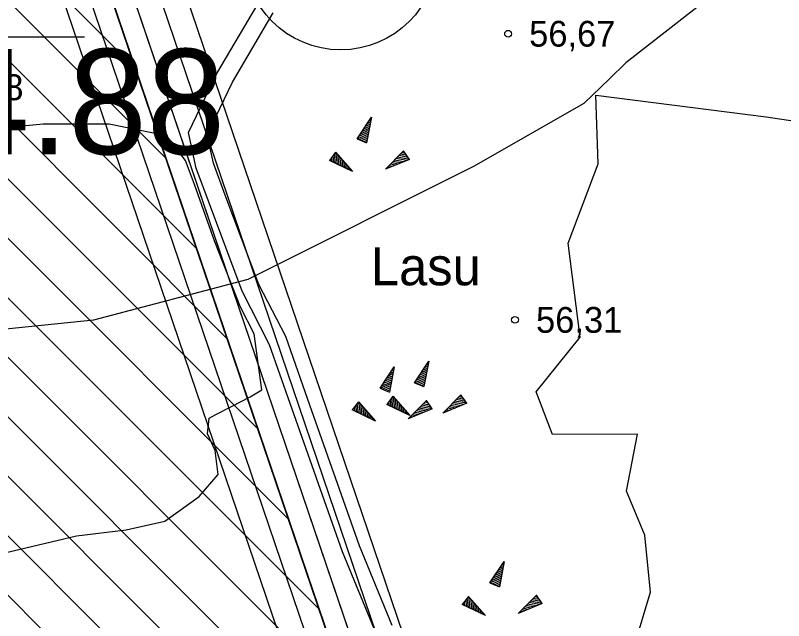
# Model space of a CAD drawing. Extents: x 532503 to 539665, y 6557663 to 6561526.
# Drawn here: x 534874.3 to 534947.4, y 6559690.1 to 6559747.6 of the extents above; entities that cross this region are included whole.
import ezdxf

# ---------------------------------------------------------------- set-up
doc = ezdxf.new("R2010")
doc.units = 0
for name, color, linetype in [('Default', 7, 'Continuous'), ('HALJASTUS', 7, 'Continuous'), ('illumineerimisjooned', 7, 'Continuous'), ('jääkpaksus', 7, 'Continuous'), ('Kaevandatud ala', 7, 'Continuous'), ('kataster', 7, 'Continuous'), ('KORGUS-EH2000', 7, 'Continuous'), ('Lamami horisontaal_EH2000', 7, 'Continuous'), ('ME_aktiivne', 7, 'Continuous'), ('MOOTKORG', 7, 'Continuous'), ('PIIR', 7, 'Continuous'), ('PIIR_me', 7, 'Continuous'), ('Plokid', 7, 'Continuous'), ('RELJEEF', 7, 'Continuous'), ('TM_aktiivne', 7, 'Continuous')]:
    doc.layers.add(name, color=color, linetype=linetype)

# ---------------------------------------------------------------- blocks, each defined once
blk = doc.blocks.new('POINT_DISPLAY')
at = {"layer": 'Default'}
blk.add_line((0, 0), (0, 0), dxfattribs=at)

msp = doc.modelspace()

# ---------------------------------------------------------------- linework, layer by layer
at = {"layer": 'illumineerimisjooned'}
for points in [[(534195.15, 6559981.187), (534198.982, 6559981.551), (535160.123, 6560071.768), (535418.528, 6559993.818), (535458.873, 6559929.252), (535494.628, 6559867.696), (535482.599, 6559826.001), (535251.738, 6559649.676), (535250.358, 6559648.526), (535180.445, 6559687.333), (534941.147, 6559814.594), (534876.935, 6559774.719), (534959.617, 6559531.323), (534733.77, 6559483.152), (534375.905, 6559461.866), (534195.514, 6559444.474)], [(535103.273, 6559501.74), (534971.344, 6559496.804), (534876.945, 6559774.719), (534941.147, 6559814.604), (535178.869, 6559688.171)], [(534960.711, 6559535.564), (534879.83, 6559773.686), (534941.24, 6559811.836), (535177.962, 6559685.935)]]:
    msp.add_lwpolyline(points, dxfattribs=at)
msp.add_lwpolyline([(534967.673, 6560049.69), (534974.155, 6559828.082), (535058.693, 6559883.051), (535223.499, 6560002.448), (535218.56, 6560049.918), (535415.933, 6559990.422), (535455.447, 6559927.188), (535490.312, 6559867.164), (535479.121, 6559828.379), (535249.574, 6559653.049), (535182.36, 6559690.845), (534940.993, 6559819.216), (534872.135, 6559776.441), (534954.369, 6559534.338), (534950.911, 6559533.67), (534733.22, 6559487.117), (534375.585, 6559465.864), (534199.951, 6559448.922), (533951.788, 6559660.129), (534200.214, 6559977.649), (534931.627, 6560046.309)], close=True, dxfattribs=at)
at = {"layer": 'jääkpaksus'}
msp.add_lwpolyline([(534864.921, 6559740.761), (534864.921, 6559745.561), (534880.921, 6559745.561)], dxfattribs=at)
at = {"layer": 'Kaevandatud ala'}
for p, q in [((534849.041, 6559779.274), (534885.756, 6559742.56)), ((534844.74, 6559777.919), (534888.666, 6559733.993)), ((534948.504, 6559557.824), (534874.54, 6559775.58)), ((534851.209, 6559765.793), (534891.575, 6559725.426)), ((534846.438, 6559764.906), (534894.485, 6559716.86)), ((534841.418, 6559764.27), (534897.395, 6559708.293)), ((534846.197, 6559748.178), (534903.214, 6559691.16)), ((534841.524, 6559747.193), (534906.124, 6559682.593)), ((534852.844, 6559747.187), (534900.305, 6559699.727)), ((534837.222, 6559745.838), (534909.034, 6559674.027)), ((534832.452, 6559744.952), (534911.944, 6559665.46)), ((534821.764, 6559744.326), (534917.763, 6559648.327)), ((534827.089, 6559744.658), (534914.853, 6559656.894))]:
    msp.add_line(p, q, dxfattribs=at)
at = {"layer": 'kataster'}
for points in [[(533947.7, 6559658.95), (533949.2, 6559955.8), (534198.28, 6559979.48), (535159.89, 6560069.73), (535417.31, 6559992.13), (535457.22, 6559928.24), (535504.86, 6559846.09), (535250.3, 6559650.84), (535181.52, 6559689.04), (534941.15, 6559817.08), (534874.65, 6559775.26), (534957.01, 6559532.73), (534735.22, 6559485.45), (534375.71, 6559463.85), (534199.28, 6559446.9), (534122.84, 6559439.44), (534110.45, 6559447.36), (534092.53, 6559453.94), (534085.13, 6559454.75)], [(534957.01, 6559532.73), (534874.65, 6559775.26), (534941.15, 6559817.08), (535181.52, 6559689.04), (535104.64, 6559499.79), (534969.93, 6559494.75)]]:
    msp.add_lwpolyline(points, close=True, dxfattribs=at)
at = {"layer": 'KORGUS-EH2000'}
for centre in [(534921.171, 6559745.851), (534921.824, 6559718.655)]:
    msp.add_circle(centre, 0.32, dxfattribs=at)
at = {"layer": 'Lamami horisontaal_EH2000'}
msp.add_lwpolyline([(534948.61, 6559756.736), (534944.621, 6559753.17), (534942.275, 6559750.842), (534932.369, 6559743.101), (534930.796, 6559741.554), (534928.37, 6559739.225), (534917.897, 6559733.223), (534896.45, 6559722.499), (534881.767, 6559718.623), (534861.677, 6559716.58), (534841.918, 6559714.402), (534826.048, 6559713.586), (534808.234, 6559712.485), (534790.42, 6559711.19), (534772.606, 6559709.668)], dxfattribs=at)
at = {"layer": 'ME_aktiivne'}
msp.add_lwpolyline([(534874.54, 6559775.58), (534941.07, 6559816.91), (535181.4, 6559689.09), (535131.71, 6559566.56), (534957, 6559532.81)], close=True, dxfattribs=at)
at = {"layer": 'PIIR'}
msp.add_circle((534905.265, 6559753.513), 9.2, dxfattribs=at)
at = {"layer": 'PIIR_me'}
msp.add_lwpolyline([(534441.63, 6560002.32), (534688.17, 6560025.46), (534931.44, 6560048.3), (534969.61, 6560051.877), (534976.05, 6559831.7), (535057.56, 6559884.7), (535221.39, 6560003.39), (535216.26, 6560052.7), (535417.23, 6559992.12), (535457.16, 6559928.22), (535492.47, 6559867.43), (535480.86, 6559827.19), (535250.12, 6559650.95), (535250.12, 6559650.95), (535181.4, 6559689.09), (534941.07, 6559816.91), (534874.54, 6559775.58), (534957, 6559532.81), (534951.31, 6559531.71), (534733.49, 6559485.13), (534485.11, 6559470.37)], dxfattribs=at)
at = {"layer": 'Plokid'}
for points in [[(535473.831, 6559827.358), (535249.729, 6559656.195), (535183.501, 6559692.956), (534940.9, 6559821.974), (534869.24, 6559777.474), (534950.465, 6559538.369)], [(534961.532, 6559540.611), (534882.716, 6559772.654), (534941.333, 6559809.068), (535174.925, 6559684.832)]]:
    msp.add_lwpolyline(points, dxfattribs=at)
at = {"layer": 'RELJEEF'}
for p, q in [((534906.833, 6559735.866), (534908.177, 6559737.914)), ((534908.177, 6559737.914), (534907.729, 6559735.498)), ((534907.777, 6559737.306), (534908.097, 6559737.434)), ((534907.937, 6559737.546), (534908.129, 6559737.626)), ((534908.097, 6559737.786), (534908.161, 6559737.818)), ((534907.153, 6559736.346), (534907.953, 6559736.682)), ((534907.313, 6559736.586), (534907.713, 6559736.762)), ((534907.473, 6559736.826), (534908.017, 6559737.066)), ((534907.633, 6559737.066), (534908.049, 6559737.258)), ((534907.713, 6559736.762), (534907.985, 6559736.874)), ((534906.833, 6559735.866), (534907.873, 6559736.314)), ((534906.993, 6559736.106), (534907.905, 6559736.49)), ((534907.041, 6559735.786), (534907.841, 6559736.122)), ((534906.833, 6559735.866), (534907.729, 6559735.498)), ((534907.249, 6559735.69), (534907.809, 6559735.93)), ((534907.473, 6559735.61), (534907.777, 6559735.738)), ((534907.681, 6559735.53), (534907.729, 6559735.546)), ((534904.781, 6559734.584), (534904.189, 6559733.816)), ((534904.781, 6559734.584), (534906.397, 6559732.76)), ((534904.781, 6559734.584), (534904.925, 6559733.464)), ((534909.515, 6559732.968), (534911.243, 6559734.712)), ((534911.403, 6559734.472), (534911.083, 6559734.536)), ((534911.275, 6559734.664), (534911.211, 6559734.664)), ((534911.787, 6559733.912), (534911.243, 6559734.712)), ((534906.397, 6559732.76), (534904.189, 6559733.816)), ((534904.221, 6559733.864), (534904.237, 6559733.8)), ((534904.365, 6559734.04), (534904.413, 6559733.72)), ((534904.509, 6559734.232), (534904.589, 6559733.64)), ((534904.637, 6559734.408), (534904.749, 6559733.544)), ((534904.973, 6559734.376), (534905.101, 6559733.384)), ((534905.165, 6559734.152), (534905.277, 6559733.304)), ((534905.357, 6559733.944), (534905.405, 6559733.496)), ((534911.787, 6559733.912), (534909.515, 6559732.968)), ((534911.243, 6559733.688), (534910.395, 6559733.848)), ((534911.515, 6559733.8), (534910.539, 6559733.992)), ((534911.787, 6559733.912), (534910.667, 6559734.12)), ((534911.659, 6559734.088), (534910.811, 6559734.264)), ((534911.531, 6559734.28), (534910.939, 6559734.392)), ((534905.405, 6559733.496), (534905.453, 6559733.208)), ((534905.533, 6559733.72), (534905.629, 6559733.128)), ((534905.725, 6559733.512), (534905.789, 6559733.048)), ((534905.917, 6559733.288), (534905.965, 6559732.968)), ((534906.109, 6559733.08), (534906.141, 6559732.872)), ((534909.643, 6559733.016), (534909.595, 6559733.032)), ((534909.915, 6559733.128), (534909.723, 6559733.176)), ((534910.187, 6559733.24), (534909.851, 6559733.304)), ((534910.443, 6559733.352), (534909.995, 6559733.448)), ((534910.715, 6559733.464), (534910.123, 6559733.576)), ((534910.555, 6559733.656), (534910.267, 6559733.72)), ((534910.987, 6559733.576), (534910.555, 6559733.656)), ((534906.301, 6559732.856), (534906.317, 6559732.792)), ((534909.008, 6559712.152), (534910.352, 6559714.2)), ((534910.352, 6559714.2), (534909.904, 6559711.784)), ((534910.272, 6559714.072), (534910.336, 6559714.104)), ((534912.281, 6559712.68), (534913.625, 6559714.728)), ((534913.081, 6559713.88), (534913.497, 6559714.072)), ((534913.625, 6559714.728), (534913.177, 6559712.312)), ((534913.225, 6559714.12), (534913.545, 6559714.248)), ((534913.385, 6559714.36), (534913.577, 6559714.44)), ((534913.545, 6559714.6), (534913.609, 6559714.632)), ((534909.648, 6559713.112), (534910.192, 6559713.352)), ((534909.808, 6559713.352), (534910.224, 6559713.544)), ((534909.952, 6559713.592), (534910.272, 6559713.72)), ((534910.112, 6559713.832), (534910.304, 6559713.912)), ((534912.601, 6559713.16), (534913.401, 6559713.496)), ((534912.761, 6559713.4), (534913.161, 6559713.576)), ((534912.921, 6559713.64), (534913.465, 6559713.88)), ((534913.161, 6559713.576), (534913.433, 6559713.688)), ((534909.008, 6559712.152), (534910.048, 6559712.6)), ((534909.168, 6559712.392), (534910.08, 6559712.776)), ((534909.328, 6559712.632), (534910.128, 6559712.968)), ((534909.488, 6559712.872), (534909.888, 6559713.048)), ((534909.888, 6559713.048), (534910.16, 6559713.16)), ((534912.281, 6559712.68), (534913.321, 6559713.128)), ((534912.281, 6559712.68), (534913.177, 6559712.312)), ((534912.441, 6559712.92), (534913.353, 6559713.304)), ((534912.489, 6559712.6), (534913.289, 6559712.936)), ((534912.697, 6559712.504), (534913.257, 6559712.744)), ((534909.008, 6559712.152), (534909.904, 6559711.784)), ((534909.216, 6559712.072), (534910.016, 6559712.408)), ((534909.424, 6559711.976), (534909.984, 6559712.216)), ((534909.648, 6559711.896), (534909.952, 6559712.024)), ((534912.921, 6559712.424), (534913.225, 6559712.552)), ((534913.129, 6559712.344), (534913.177, 6559712.36)), ((534910.229, 6559711.397), (534909.637, 6559710.629)), ((534909.856, 6559711.816), (534909.904, 6559711.832)), ((534910.085, 6559711.221), (534910.197, 6559710.357)), ((534910.229, 6559711.397), (534911.845, 6559709.573)), ((534910.229, 6559711.397), (534910.373, 6559710.277)), ((534910.421, 6559711.189), (534910.549, 6559710.197)), ((534914.963, 6559709.781), (534916.691, 6559711.525)), ((534916.979, 6559711.093), (534916.387, 6559711.205)), ((534916.851, 6559711.285), (534916.531, 6559711.349)), ((534916.723, 6559711.477), (534916.659, 6559711.477)), ((534917.235, 6559710.725), (534916.691, 6559711.525)), ((534906.956, 6559710.869), (534906.364, 6559710.101)), ((534906.684, 6559710.517), (534906.764, 6559709.925)), ((534906.812, 6559710.693), (534906.924, 6559709.829)), ((534906.956, 6559710.869), (534908.572, 6559709.045)), ((534906.956, 6559710.869), (534907.1, 6559709.749)), ((534907.148, 6559710.661), (534907.276, 6559709.669)), ((534907.34, 6559710.437), (534907.452, 6559709.589)), ((534911.845, 6559709.573), (534909.637, 6559710.629)), ((534909.669, 6559710.677), (534909.685, 6559710.613)), ((534909.813, 6559710.853), (534909.861, 6559710.533)), ((534909.957, 6559711.045), (534910.037, 6559710.453)), ((534910.613, 6559710.965), (534910.725, 6559710.117)), ((534910.805, 6559710.757), (534910.853, 6559710.309)), ((534910.981, 6559710.533), (534911.077, 6559709.941)), ((534911.689, 6559709.253), (534913.417, 6559710.997)), ((534913.961, 6559710.197), (534912.841, 6559710.405)), ((534913.833, 6559710.373), (534912.985, 6559710.549)), ((534913.705, 6559710.565), (534913.113, 6559710.677)), ((534913.577, 6559710.757), (534913.257, 6559710.821)), ((534913.449, 6559710.949), (534913.385, 6559710.949)), ((534913.961, 6559710.197), (534913.417, 6559710.997)), ((534917.235, 6559710.725), (534914.963, 6559709.781)), ((534916.003, 6559710.469), (534915.715, 6559710.533)), ((534916.691, 6559710.501), (534915.843, 6559710.661)), ((534916.963, 6559710.613), (534915.987, 6559710.805)), ((534916.435, 6559710.389), (534916.003, 6559710.469)), ((534917.235, 6559710.725), (534916.115, 6559710.933)), ((534917.107, 6559710.901), (534916.259, 6559711.077)), ((534908.572, 6559709.045), (534906.364, 6559710.101)), ((534906.396, 6559710.149), (534906.412, 6559710.085)), ((534906.54, 6559710.325), (534906.588, 6559710.005)), ((534907.532, 6559710.229), (534907.58, 6559709.781)), ((534907.58, 6559709.781), (534907.628, 6559709.493)), ((534907.708, 6559710.005), (534907.804, 6559709.413)), ((534907.9, 6559709.797), (534907.964, 6559709.333)), ((534910.853, 6559710.309), (534910.901, 6559710.021)), ((534911.173, 6559710.325), (534911.237, 6559709.861)), ((534911.365, 6559710.101), (534911.413, 6559709.781)), ((534911.557, 6559709.893), (534911.589, 6559709.685)), ((534913.961, 6559710.197), (534911.689, 6559709.253)), ((534911.749, 6559709.669), (534911.765, 6559709.605)), ((534912.617, 6559709.637), (534912.169, 6559709.733)), ((534912.889, 6559709.749), (534912.297, 6559709.861)), ((534912.729, 6559709.941), (534912.441, 6559710.005)), ((534913.417, 6559709.973), (534912.569, 6559710.133)), ((534913.689, 6559710.085), (534912.713, 6559710.277)), ((534913.161, 6559709.861), (534912.729, 6559709.941)), ((534915.091, 6559709.829), (534915.043, 6559709.845)), ((534915.363, 6559709.941), (534915.171, 6559709.989)), ((534915.635, 6559710.053), (534915.299, 6559710.117)), ((534915.891, 6559710.165), (534915.443, 6559710.261)), ((534916.163, 6559710.277), (534915.571, 6559710.389)), ((534908.092, 6559709.573), (534908.14, 6559709.253)), ((534908.284, 6559709.365), (534908.316, 6559709.157)), ((534908.476, 6559709.141), (534908.492, 6559709.077)), ((534911.817, 6559709.301), (534911.769, 6559709.317)), ((534912.089, 6559709.413), (534911.897, 6559709.461)), ((534912.361, 6559709.525), (534912.025, 6559709.589)), ((534919.447, 6559693.659), (534920.791, 6559695.707)), ((534920.791, 6559695.707), (534920.343, 6559693.291)), ((534920.391, 6559695.099), (534920.711, 6559695.227)), ((534920.551, 6559695.339), (534920.743, 6559695.419)), ((534920.711, 6559695.579), (534920.775, 6559695.611)), ((534919.767, 6559694.139), (534920.567, 6559694.475)), ((534919.927, 6559694.379), (534920.327, 6559694.555)), ((534920.087, 6559694.619), (534920.631, 6559694.859)), ((534920.247, 6559694.859), (534920.663, 6559695.051)), ((534920.327, 6559694.555), (534920.599, 6559694.667)), ((534919.447, 6559693.659), (534920.487, 6559694.107)), ((534919.447, 6559693.659), (534920.343, 6559693.291)), ((534919.607, 6559693.899), (534920.519, 6559694.283)), ((534919.655, 6559693.579), (534920.455, 6559693.915)), ((534919.863, 6559693.483), (534920.423, 6559693.723)), ((534920.087, 6559693.403), (534920.391, 6559693.531)), ((534920.295, 6559693.323), (534920.343, 6559693.339)), ((534917.395, 6559692.377), (534916.803, 6559691.609)), ((534917.251, 6559692.201), (534917.363, 6559691.337)), ((534917.395, 6559692.377), (534919.011, 6559690.553)), ((534917.395, 6559692.377), (534917.539, 6559691.257)), ((534917.587, 6559692.169), (534917.715, 6559691.177)), ((534922.129, 6559690.761), (534923.857, 6559692.505)), ((534924.145, 6559692.073), (534923.553, 6559692.185)), ((534924.017, 6559692.265), (534923.697, 6559692.329)), ((534923.889, 6559692.457), (534923.825, 6559692.457)), ((534924.401, 6559691.705), (534923.857, 6559692.505)), ((534919.011, 6559690.553), (534916.803, 6559691.609)), ((534916.835, 6559691.657), (534916.851, 6559691.593)), ((534916.979, 6559691.833), (534917.027, 6559691.513)), ((534917.123, 6559692.025), (534917.203, 6559691.433)), ((534917.779, 6559691.945), (534917.891, 6559691.097)), ((534917.971, 6559691.737), (534918.019, 6559691.289)), ((534918.147, 6559691.513), (534918.243, 6559690.921)), ((534924.401, 6559691.705), (534922.129, 6559690.761)), ((534923.169, 6559691.449), (534922.881, 6559691.513)), ((534923.857, 6559691.481), (534923.009, 6559691.641)), ((534924.129, 6559691.593), (534923.153, 6559691.785)), ((534923.601, 6559691.369), (534923.169, 6559691.449)), ((534924.401, 6559691.705), (534923.281, 6559691.913)), ((534924.273, 6559691.881), (534923.425, 6559692.057)), ((534918.019, 6559691.289), (534918.067, 6559691.001)), ((534918.339, 6559691.305), (534918.403, 6559690.841)), ((534918.531, 6559691.081), (534918.579, 6559690.761)), ((534918.723, 6559690.873), (534918.755, 6559690.665)), ((534922.257, 6559690.809), (534922.209, 6559690.825)), ((534922.529, 6559690.921), (534922.337, 6559690.969)), ((534922.801, 6559691.033), (534922.465, 6559691.097)), ((534923.057, 6559691.145), (534922.609, 6559691.241)), ((534923.329, 6559691.257), (534922.737, 6559691.369)), ((534918.915, 6559690.649), (534918.931, 6559690.585))]:
    msp.add_line(p, q, dxfattribs=at)
for points in [[(534908.464, 6559689.214), (534905.444, 6559696.617), (534900.464, 6559710.705), (534898.494, 6559716.278), (534895.907, 6559721.373), (534892.692, 6559729.929), (534891.528, 6559733.076), (534890.798, 6559736.468), (534893.485, 6559742.058), (534897.376, 6559748.671)], [(534910.144, 6559689.609), (534907.042, 6559697.192), (534902.135, 6559711.076), (534900.041, 6559717.086), (534897.488, 6559722.014), (534894.295, 6559730.496), (534893.162, 6559733.55), (534892.579, 6559736.257), (534894.984, 6559741.258), (534898.85, 6559747.83)], [(534935.057, 6559619.238), (534934.558, 6559624.118), (534936.105, 6559629.287), (534948.1, 6559665.369), (534945.174, 6559676.289), (534942.529, 6559678.948), (534937.86, 6559679.723), (534932.296, 6559680.704), (534932.876, 6559686.664), (534934.705, 6559692.765), (534934.158, 6559698.207), (534932.438, 6559702.379), (534933.479, 6559707.803), (534925.389, 6559707.773), (534923.826, 6559711.824), (534928.008, 6559717.026), (534926.874, 6559725.946), (534929.72, 6559733.499), (534929.509, 6559740.024), (534945.69, 6559737.942), (534953.976, 6559736.717)], [(534888.706, 6559736.157), (534883.266, 6559737.261), (534876.998, 6559737.256), (534874.032, 6559736.971), (534867.685, 6559735.543), (534861.484, 6559732.298), (534853.872, 6559726.838), (534840.066, 6559721.88), (534826.892, 6559714.144), (534815.845, 6559709.003), (534799.6, 6559700.543), (534787.872, 6559693.35)], [(534884.881, 6559698.697), (534888.559, 6559699.537), (534891.825, 6559701.857), (534893.622, 6559703.962), (534893.34, 6559706.23), (534892.601, 6559707.827), (534892.767, 6559709.317), (534893.391, 6559709.656), (534894.874, 6559710.43), (534896.673, 6559711.357), (534897.778, 6559711.994), (534897.048, 6559717.314), (534895.747, 6559719.867), (534893.301, 6559726.078), (534891.369, 6559731.528), (534890.515, 6559733.794), (534888.706, 6559736.157)], [(534869.29, 6559695.554), (534880.167, 6559698.13), (534884.881, 6559698.697)]]:
    msp.add_lwpolyline(points, dxfattribs=at)
at = {"layer": 'TM_aktiivne'}
for points in [[(535159.92, 6560069.74), (535417.23, 6559992.12), (535457.16, 6559928.22), (535492.47, 6559867.43), (535480.86, 6559827.19), (535250.49, 6559651.24), (535250.13, 6559650.94), (535181.4, 6559689.09), (534941.07, 6559816.9), (534874.53, 6559775.58), (534957, 6559532.81), (534733.5, 6559485.14), (534375.75, 6559463.86), (534199.32, 6559446.85), (534124.95, 6559439.68), (533949.03, 6559659.85), (533949.15, 6559955.79), (534199.17, 6559979.56)], [(534874.54, 6559775.58), (534941.07, 6559816.91), (535181.4, 6559689.09), (535104.64, 6559499.79), (534969.93, 6559494.75)]]:
    msp.add_lwpolyline(points, close=True, dxfattribs=at)

# ---------------------------------------------------------------- block references
at = {"layer": 'RELJEEF', "xscale": 160, "yscale": 160}
for p in [(534906.833, 6559735.866), (534904.781, 6559734.584), (534911.787, 6559733.912), (534912.281, 6559712.68), (534909.008, 6559712.152), (534910.229, 6559711.397), (534906.956, 6559710.869), (534917.235, 6559710.725), (534913.961, 6559710.197), (534919.447, 6559693.659), (534917.395, 6559692.377), (534924.401, 6559691.705)]:
    msp.add_blockref('POINT_DISPLAY', p, dxfattribs=at)

# ---------------------------------------------------------------- texts
at = {"layer": 'HALJASTUS'}
msp.add_text('Lasu', height=3.6, dxfattribs=at).set_placement((534908.135, 6559721.941))
at = {"layer": 'KORGUS-EH2000'}
for s, p in [('56,67 ', (534923.171, 6559744.626)), ('64,98 ', (534866.921, 6559739.536)), ('56,31 ', (534923.824, 6559717.43))]:
    msp.add_text(s, height=2.45, dxfattribs=at).set_placement(p)
at = {"layer": 'MOOTKORG'}
msp.add_text('64.88', height=10, dxfattribs=at).set_placement((534860.811, 6559734.399))

doc.saveas('drawing.dxf')
